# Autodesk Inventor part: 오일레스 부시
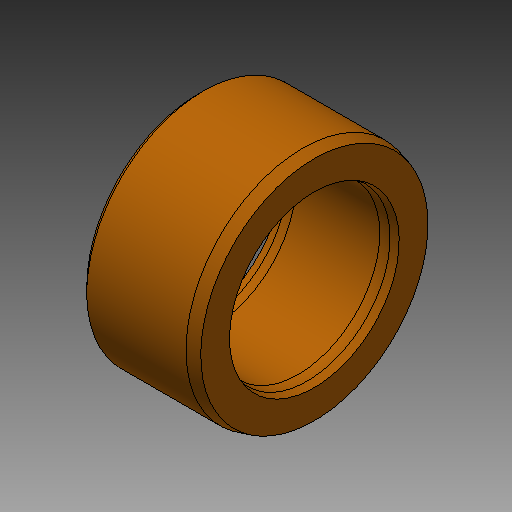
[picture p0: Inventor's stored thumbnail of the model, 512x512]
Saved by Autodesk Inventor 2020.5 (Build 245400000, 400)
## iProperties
Created: 2024-02
Part Number: 오일레스 부시
Material: 강철, 합금
Document SubType Name: Modeling
Designer: mdu-01
Density: 1 g/cm^3
Appearance: 주황색
Author: mdu-01
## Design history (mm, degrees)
sketch "스케치1"
  geometry: L1 (0, 0)-(10, 0); L2 (1.395, 7)-(8.605, 7); L3 (10, 7.268)-(10, 9.732); L4 (9, 10)-(0.5, 10); L5 (0, 9.5)-(0, 7.268); L6 (9, 10)-(10, 9.732); L7 (9.381, 7.102)-(10, 7.268); L8 (0.619, 7.102)-(0, 7.268); L9 (0.5, 10)-(0, 9.5); A1 r 3 centre (1.395, 10) between (0.619, 7.102) and (1.395, 7); A2 r 3 centre (8.605, 10) between (8.605, 7) and (9.381, 7.102); 6 further points
  constraints: 18 end point, 14 point on line, 4 point on circle, 4 tangent, 2 centre point, 2 horizontal, 2 parallel, 1 equal radius, 1 perpendicular
  dimensions: "d0" = 10 distance of L1.start L1.end; "d1" = 14 diameter of L2 L1; "d2" = 20 diameter of L4 L1; "d3" = 1 distance of L4.start point (10, 10); "d4" = 15 deg angle of L4 L6; "d5" = 1 distance of point (9, 7) point (10, 7) (= d3); "d6" = 15 deg angle of L2 L7 (= d4); "d7" = 1 distance of point (1, 7) point (0, 7) (= d3); "d8" = 15 deg angle of L2 L8 (= d4); "d9" = 3 radius of A1; "d10" = 0.5 distance of L4.end point (0, 10); "d11" = 0.5 distance of L5.start point (0, 10) (= d10)
revolve "회전1" sketch "스케치1" stored, may be unused: angle "d12" = 90 deg
node "솔리드1"
